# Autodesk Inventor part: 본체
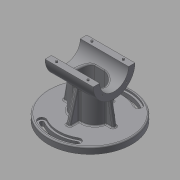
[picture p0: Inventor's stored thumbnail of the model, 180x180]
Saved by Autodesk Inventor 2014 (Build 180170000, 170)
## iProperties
Created: 2015-12
Part Number: 본체
Material: 일반
Document SubType Name: Modeling
Designer: mduedu
Density: 2.71 g/cm^3
Appearance: 기본값
Author: mduedu
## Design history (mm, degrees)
sketch "스케치1"
  geometry: C1 r 65 at (0, 0); 1 further point
  constraints: 1 centre point, 1 coincident
  dimensions: "d124" = 130 diameter of C1
extrude "돌출1" new body sketch "스케치1" distance "d3" = 10; taper "d4" = 0 deg
sketch "스케치2"
  geometry: C1 r 32.5 at (80, 0); 1 further point
  constraints: 1 centre point, 1 horizontal alignment
  dimensions: "d5" = 65 diameter of C1; "d125" = 80 distance of C1.centre point (0, 0)
extrude "돌출2" join sketch "스케치2" stored distance "d7" = 75; taper "d8" = 0 deg
sketch "스케치3"
  geometry: L1 (-27.5, -20)-(27.5, -20); L2 (27.5, -20)-(27.5, 20); L3 (27.5, 20)-(-27.5, 20); L4 (-27.5, 20)-(-27.5, -20); L5 (-27.5, -20)-(27.5, 20); L6 (27.5, -20)-(-27.5, 20); 1 further point
  constraints: 12 end point, 2 midpoint, 2 parallel, 1 horizontal, 1 perpendicular
  dimensions: "d9" = 55 distance of L2.end L3.end; "d11" = 40 distance of L1.end L2.end
extrude "돌출3" new body sketch "스케치3" stored distance "d12" = 75; taper "d13" = 0 deg
fillet "모깎기1"
fillet "모깎기2"
feature "결합1"
  node "솔리드2"
sketch "스케치4"
  geometry: L1 (-37.5, 47.5)-(37.5, 47.5) reference; L2 (32.5, 47.5)-(39.112, 10); L3 (37.5, 47.5)-(37.5, 112.5) reference; L4 (65, 10)-(-65, 10) reference; 1 further point
  constraints: 2 end point, 2 point on line
  dimensions: "d15" = 5 distance from line of L2.start L3; "d126" = 80 deg angle of L2 L1
sketch "스케치5"
  geometry: L1 (10, 35)-(56.569, 22.522); L2 (10, -65)-(10, 65) reference; L3 (10, 20)-(54.383, 20) reference; A1 r 32.5 centre (80, 0) between (56.569, 22.522) and (54.383, 20) reference; 1 further point
  constraints: 2 end point, 1 point on circle, 1 point on line
  dimensions: "d127" = 75 deg angle of L1 L2; "d128" = 15 distance of L1.start L3.start
feature "리브1" dims "d19" = 1, "d20" = 6, "d21" = 0, "d22" = 0, "d23" = 1, "d24" = 1
feature "리브2" dims "d25" = 1, "d26" = 6, "d27" = 0, "d28" = 0, "d29" = 1, "d30" = 1
fillet "모깎기4" dims "d31" = 2
fillet "모깎기5" dims "d32" = 2
fillet "모깎기6" dims "d33" = 2
fillet "모깎기7" dims "d41" = 2
hole "구멍2" diameter "d44" = 45; stored, may be unused: countersink angle "d48" = 90 deg, drill point angle "d50" = 118 deg; dims "d42" = 10, "d43" = 10, "d45" = 6, "d46" = 4, "d47" = 2, "d49" = 8
sketch "스케치7" dims "d52" = 26.5
  geometry: L1 (0, 0)-(32.5, 0); L2 (0, 0)-(22.981, 22.981); A1 r 32.5 centre (0, 0) between (32.5, 0) and (22.981, 22.981) reference; 3 further points
  constraints: 4 end point, 2 point on circle, 1 coincident, 1 horizontal, 1 point on line, 3 other
  dimensions: "d51" = 45 deg angle of L2 L1
hole "구멍3" sketch "스케치7" at (18.738, 18.738) diameter "d54" = 2.459; stored, may be unused: countersink angle "d58" = 90 deg, drill point angle "d60" = 118 deg; dims "d55" = 8, "d56" = 4, "d57" = 2, "d59" = 10
sketch "스케치9"
  geometry: L1 (-75, 82.5)-(75, 82.5); L2 (75, 82.5)-(75, 0); L3 (75, 0)-(-75, 0); L4 (-75, 0)-(-75, 82.5); C1 r 32.5 at (0, 0) reference; 2 further points
  constraints: 8 end point, 2 parallel, 1 coincident, 1 horizontal, 1 midpoint, 1 perpendicular
  dimensions: "d71" = 50 distance edge to line of C1 L1; "d116" = 150 distance between parallel lines of L2 L4
extrude "돌출5" cut sketch "스케치9" stored distance "d73" = 0; taper "d74" = 0 deg
node "작업 평면1"
sketch "스케치10"
  geometry: L1 (-7.5, 15)-(7.5, 15); L2 (-7.5, -15)-(7.5, -15); A1 r 20 centre (-7.5, 0) between (-7.5, 20) and (-26.977, 4.545) reference; A2 r 20 centre (7.5, 0) between (26.977, 4.545) and (7.5, 20) reference; A3 r 15 centre (-7.5, 0) between (-7.5, 15) and (-7.5, -15); A4 r 15 centre (7.5, 0) between (7.5, -15) and (7.5, 15); 1 further point
  constraints: 7 point on circle, 4 end point, 4 tangent, 3 point on line, 2 centre point, 2 coincident, 1 horizontal
  dimensions: "d77" = 5 radial gap between concentric circles of A3 A1
extrude "돌출6" cut sketch "스케치10" stored distance "d78" = 50; taper "d79" = 0 deg
fillet "모깎기10" dims "d80" = 3
sketch "스케치11"
  geometry: 2 further points
  constraints: 1 coincident
hole "구멍4" sketch "스케치11" at (0, 0) diameter "d81" = 12; stored, may be unused: countersink angle "d85" = 90 deg, drill point angle "d87" = 118 deg; dims "d82" = 8, "d83" = 40, "d84" = 10, "d86" = 10
sketch "스케치12"
  geometry: C1 r 10 at (0, 0); 1 further point
  constraints: 1 centre point, 1 coincident
  dimensions: "d88" = 20 diameter of C1
extrude "돌출7" cut sketch "스케치12" distance "d89" = 5; taper "d90" = 0 deg
chamfer "모따기1" distance "d91" = 1; stored, may be unused: second distance "d92" = 2, angle "d93" = 45 deg
fillet "모깎기11" dims "d94" = 0.5
fillet "모깎기12" dims "d115" = 0.3
sketch "스케치15"
  geometry: L1 (-75, 55)-(-75, 65) reference; L2 (0, 65)-(0, 55) reference; L3 (-75, 60)-(0, 60); C1 r 1.5 at (-62, 60); 1 further point
  constraints: 2 end point, 2 midpoint, 1 centre point, 1 point on line
  dimensions: "d117" = 3 diameter of C1; "d118" = 13 distance from line of C1.centre L1
extrude "돌출8" join sketch "스케치15" distance "d119" = 1.8; taper "d120" = 0 deg
chamfer "모따기2" distance "d121" = 0.5; stored, may be unused: second distance "d122" = 2, angle "d123" = 45 deg
sketch "스케치16"
  geometry: L1 (0, 0)-(61, 0); L2 (0, 0)-(30.5, 52.828); L3 (0, 0)-(-30.5, 52.828); L4 (0, 0)-(-61, 0); A1 r 55 centre (0, 0) between (-27.5, 47.631) and (27.5, 47.631); A2 r 61 centre (0, 0) between (-30.5, 52.828) and (30.5, 52.828); A3 r 49 centre (0, 0) between (-24.5, 42.435) and (24.5, 42.435); A4 r 6 centre (-27.5, 47.631) between (-30.5, 52.828) and (-24.5, 42.435); A5 r 6 centre (27.5, 47.631) between (30.5, 52.828) and (24.5, 42.435); A6 r 49 centre (0, 0) between (24.5, 42.435) and (-24.5, 42.435); A7 r 61 centre (0, 0) between (30.5, 52.828) and (-30.5, 52.828); 1 further point
  constraints: 15 point on circle, 8 end point, 7 centre point, 2 point on line, 1 coincident, 1 horizontal, 10 other
  dimensions: "d129" = 110 diameter of A1; "d130" = 6 radial gap between concentric circles of A1 A2; "d131" = 6 radial gap between concentric circles of A3 A1; "d134" = 180 deg dimension on point (0, 0) L1.end L4.end
extrude "돌출9" cut sketch "스케치16" distance "d136" = 3; taper "d137" = 0 deg
sketch "스케치17"
  geometry: A1 r 6 centre (27.5, 47.631) between (24.5, 42.435) and (30.5, 52.828) reference; A2 r 61 centre (0, 0) between (30.5, 52.828) and (-30.5, 52.828) reference; A3 r 6 centre (-27.5, 47.631) between (-30.5, 52.828) and (-24.5, 42.435) reference; A4 r 49 centre (0, 0) between (24.5, 42.435) and (-24.5, 42.435) reference; A5 r 58 centre (0, 0) between (29, 50.229) and (-29, 50.229); A6 r 3 centre (27.5, 47.631) between (26, 45.033) and (29, 50.229); A7 r 52 centre (0, 0) between (26, 45.033) and (-26, 45.033); A8 r 3 centre (-27.5, 47.631) between (-29, 50.229) and (-26, 45.033); 1 further point
  constraints: 8 point on circle, 4 centre point, 3 other
  dimensions: "d138" = 3 radial gap between concentric circles of A5 A2
extrude "돌출10" cut sketch "스케치17" stored distance "d139" = 3; taper "d140" = 0 deg
node "솔리드1"
mirror "대칭1"
mirror "대칭2"
pattern_circular "원형 패턴1" dims angle "d62" = 360 deg
mirror "대칭3"
mirror "대칭5"
mirror "대칭6"
mirror "대칭7"
node "투영된 루프1"
